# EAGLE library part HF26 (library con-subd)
SUB-D
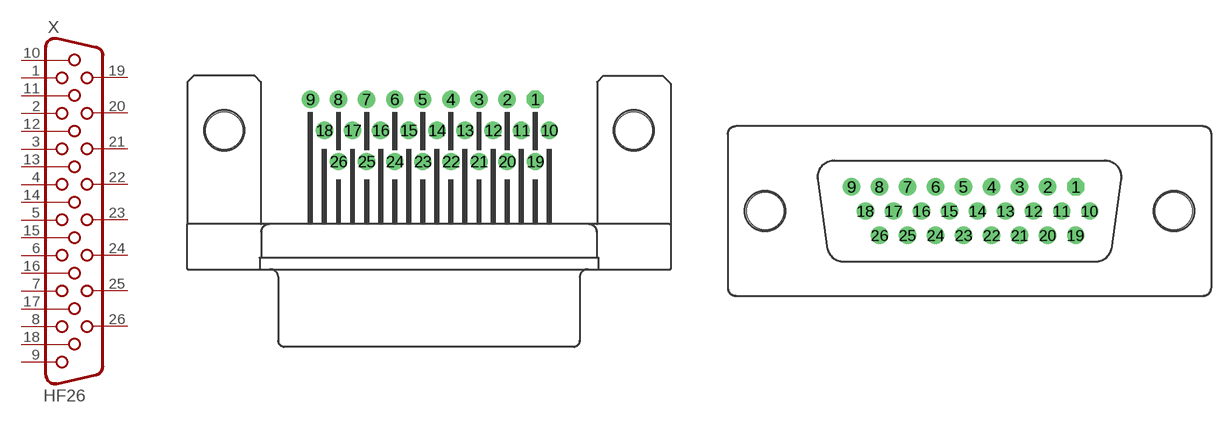
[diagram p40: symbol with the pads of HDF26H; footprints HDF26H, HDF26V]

Designator prefix X

## HF26H (OC_FARNELL: unknown; OC_NEWARK: unknown)  [HDF26H]
1  1  pas
2  2  pas
3  3  pas
4  4  pas
5  5  pas
6  6  pas
7  7  pas
8  8  pas
9  9  pas
10  10  pas
11  11  pas
12  12  pas
13  13  pas
14  14  pas
15  15  pas
16  16  pas
17  17  pas
18  18  pas
19  19  pas
20  20  pas
21  21  pas
22  22  pas
23  23  pas
24  24  pas
25  25  pas
26  26  pas

## HF26V (OC_FARNELL: unknown; OC_NEWARK: unknown)  [HDF26V]
Pads as for HDF26H

## Footprint HDF26H (pad centres in mm)
SUB-D
drill 0.9 octagon: 1 8.639,2.54
drill 0.9 round: 2 6.353,2.54; 3 4.067,2.54; 4 1.781,2.54; 5 -0.505,2.54; 6 -2.791,2.54; 7 -5.077,2.54; 8 -7.363,2.54; 9 -9.649,2.54; 10 9.782,0; 11 7.496,0; 12 5.21,0; 13 2.924,0; 14 0.638,0; 15 -1.648,0; 16 -3.934,0; 17 -6.22,0; 18 -8.506,0; 19 8.639,-2.54; 20 6.353,-2.54; 21 4.067,-2.54; 22 1.781,-2.54; 23 -0.505,-2.54; 24 -2.791,-2.54; 25 -5.077,-2.54; 26 -7.363,-2.54
hole 3 at -16.65,0
hole 3 at 16.65,0

## Footprint HDF26V (pad centres in mm)
SUB-D
drill 0.9 octagon: 1 8.658,1.98
drill 0.9 round: 2 6.372,1.98; 3 4.086,1.98; 4 1.8,1.98; 5 -0.486,1.98; 6 -2.772,1.98; 7 -5.058,1.98; 8 -7.344,1.98; 9 -9.63,1.98; 10 9.801,0; 11 7.515,0; 12 5.229,0; 13 2.943,0; 14 0.657,0; 15 -1.629,0; 16 -3.915,0; 17 -6.201,0; 18 -8.487,0; 19 8.658,-1.98; 20 6.372,-1.98; 21 4.086,-1.98; 22 1.8,-1.98; 23 -0.486,-1.98; 24 -2.772,-1.98; 25 -5.058,-1.98; 26 -7.344,-1.98
hole 3 at -16.65,0
hole 3 at 16.65,0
